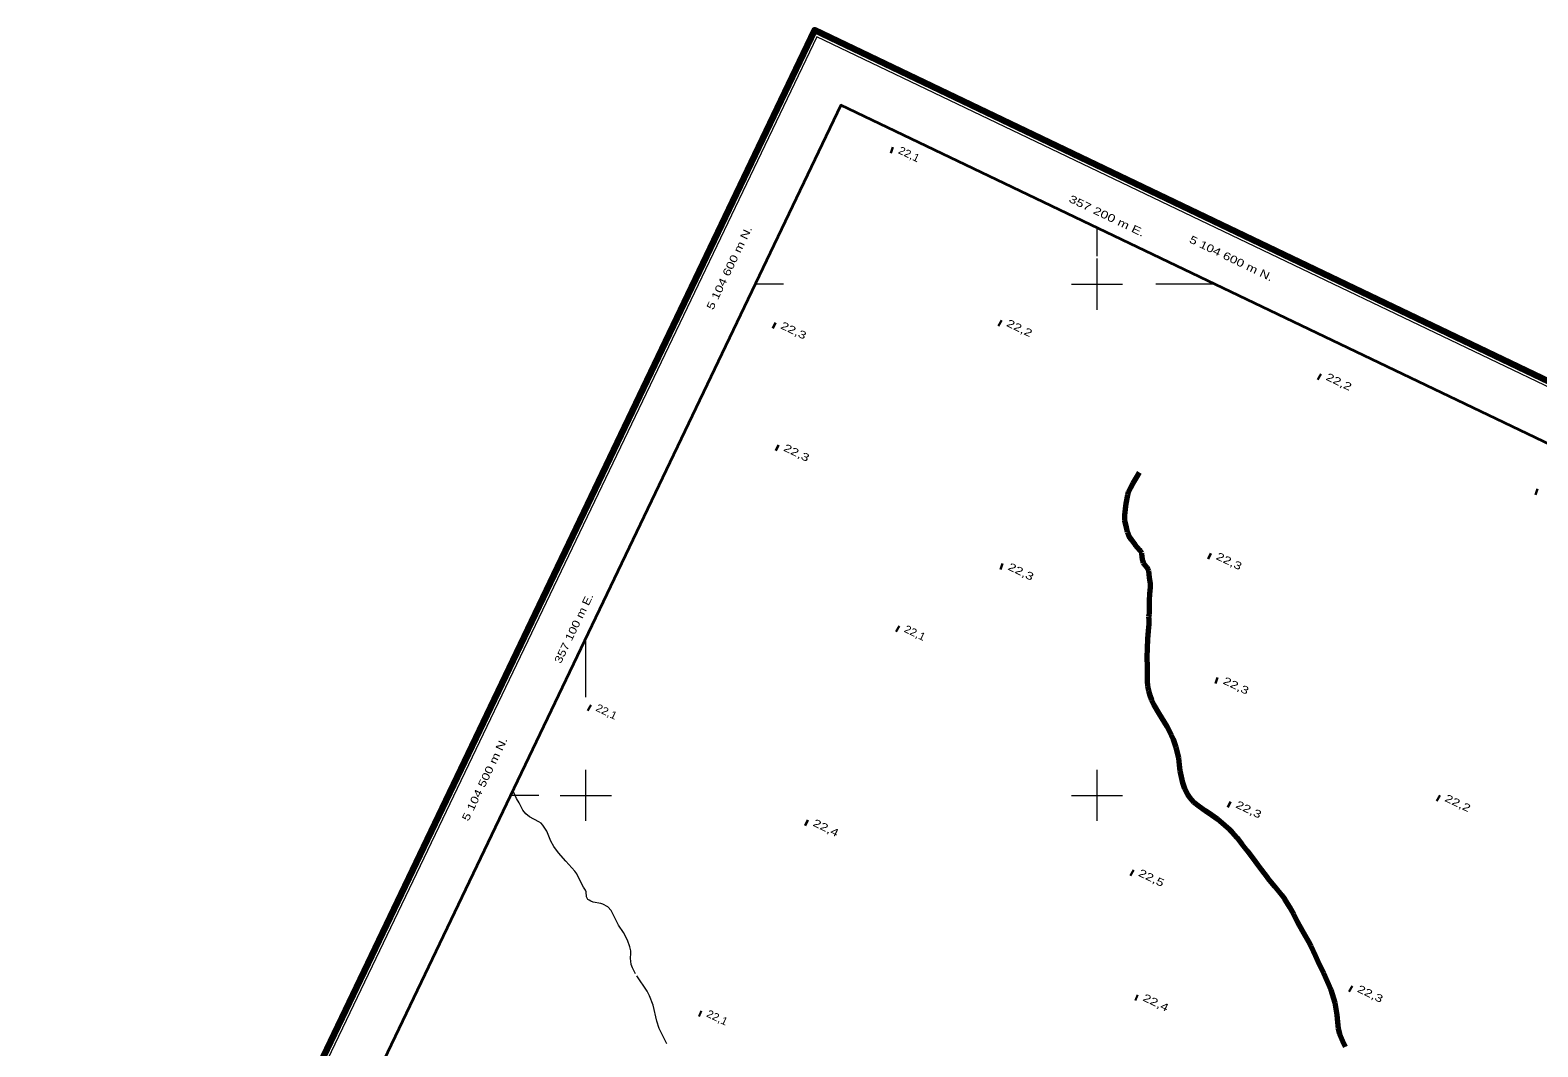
# Model space of a CAD drawing. Extents: x 356765 to 358572, y 5103174 to 5104650.
# Drawn here: x 356991.3 to 357286.2, y 5104450.8 to 5104649.7 of the extents above; entities that cross this region are included whole.
import ezdxf
from ezdxf.enums import TextEntityAlignment as Align

# ---------------------------------------------------------------- set-up
doc = ezdxf.new("R2010")
doc.units = 0
doc.header["$LTSCALE"] = 0.6
doc.linetypes.add('LONG_DASHED', pattern=[7.5, 6, -1.5])
for name, color, linetype, lineweight in [('2', 7, 'Continuous', 13), ('22', 7, 'Continuous', 35), ('3', 7, 'Continuous', 140), ('60', 7, 'Continuous', 13), ('61', 7, 'Continuous', 13)]:
    doc.layers.add(name, color=color, linetype=linetype, lineweight=lineweight)

msp = doc.modelspace()

# ---------------------------------------------------------------- linework, layer by layer
at = {"layer": '2', "linetype": 'LONG_DASHED'}
msp.add_lwpolyline([(357115.84, 5104451.38), (357114.36, 5104454.41), (357113.9, 5104455.84), (357113.16, 5104458.95), (357112.47, 5104460.83), (357112, 5104461.7), (357109.7, 5104465.13), (357109.1, 5104466.3), (357108.89, 5104466.93), (357108.78, 5104467.55), (357108.75, 5104468.12), (357108.83, 5104469.12), (357108.8, 5104469.58), (357108.6, 5104470.41), (357108.17, 5104471.66), (357107.4, 5104473.21), (357106.4, 5104474.62), (357104.95, 5104477.46), (357104.3, 5104478.19), (357103.3, 5104478.72), (357102.94, 5104478.84), (357101.44, 5104479.15), (357100.99, 5104479.29), (357100.64, 5104479.48), (357100.42, 5104479.67), (357100.25, 5104479.88), (357100.14, 5104480.16), (357100.06, 5104481.15), (357099.94, 5104481.5), (357099.56, 5104482.05), (357099.06, 5104482.92), (357098.23, 5104484.67), (357097.87, 5104485.21), (357096.08, 5104487.11), (357094.63, 5104488.78), (357093.71, 5104489.98), (357093.14, 5104491.07), (357092.37, 5104492.99), (357091.88, 5104493.82), (357091.58, 5104494.21), (357091.23, 5104494.55), (357090.81, 5104494.84), (357089, 5104495.8), (357088.27, 5104496.4), (357087.69, 5104497.15), (357086.94, 5104498.57), (357086.43, 5104499.42), (357085.82, 5104500.7), (357085.66, 5104500.98)], dxfattribs=at)
at = {"layer": '22', "linetype": 'LONG_DASHED', "lineweight": 70}
for points in [[(357210.22, 5104534.4), (357210.17, 5104534.99), (357210.24, 5104535.48), (357210.3, 5104535.79), (357210.3, 5104536.05), (357210.24, 5104537.18), (357210.26, 5104538.17), (357210.34, 5104539.38), (357210.45, 5104540.74), (357210.44, 5104541.42), (357210.28, 5104542.62), (357210.13, 5104543.94), (357210.04, 5104544.28), (357209.84, 5104544.59), (357209.29, 5104545.2), (357209.1, 5104545.51), (357208.99, 5104545.86), (357208.82, 5104546.62), (357208.76, 5104547.37), (357208.58, 5104547.76), (357208.4, 5104547.99), (357207.48, 5104549.05), (357206.72, 5104550), (357206.3, 5104550.67), (357205.99, 5104551.48), (357205.76, 5104552.38), (357205.45, 5104553.8), (357205.44, 5104554.84), (357205.6, 5104555.97), (357205.72, 5104557.12), (357206, 5104558.79), (357206.19, 5104559.3), (357206.63, 5104560.25), (357207.1, 5104561.07), (357207.86, 5104562.4), (357208.31, 5104563.18)], [(357248.61, 5104450.8), (357248.07, 5104451.92), (357247.48, 5104453.32), (357247.22, 5104454.38), (357247.08, 5104455.63), (357246.97, 5104457.09), (357246.74, 5104458.66), (357246.57, 5104459.46), (357246.1, 5104461.11), (357245.8, 5104461.94), (357245.11, 5104463.61), (357244.35, 5104465.26), (357243.54, 5104466.95), (357242.75, 5104468.72), (357241.9, 5104470.51), (357241.44, 5104471.38), (357240.49, 5104473.05), (357239.6, 5104474.55), (357239.22, 5104475.3), (357238.49, 5104476.75), (357237.69, 5104478.17), (357236.74, 5104479.68), (357236.15, 5104480.49), (357234.8, 5104482.2), (357233.42, 5104483.83), (357232.09, 5104485.49), (357231.51, 5104486.29), (357230.49, 5104487.76), (357229.44, 5104489.11), (357228.42, 5104490.42), (357227.45, 5104491.71), (357226.46, 5104492.83), (357225.96, 5104493.3), (357225, 5104494.15), (357223.54, 5104495.37), (357222.44, 5104496.16), (357221.25, 5104496.98), (357220.05, 5104497.83), (357218.97, 5104498.69), (357218.53, 5104499.13), (357218.13, 5104499.62), (357217.78, 5104500.16), (357217.2, 5104501.32), (357216.81, 5104502.48), (357216.51, 5104503.62), (357216.27, 5104504.79), (357216.13, 5104506), (357215.98, 5104507.28), (357215.7, 5104508.63), (357215.49, 5104509.37), (357214.95, 5104510.96), (357214.59, 5104511.79), (357213.73, 5104513.46), (357213.22, 5104514.3), (357212.13, 5104516.05), (357211.11, 5104517.78), (357210.7, 5104518.65), (357210.37, 5104519.55), (357210.13, 5104520.48), (357209.95, 5104521.4), (357209.88, 5104522.32), (357209.86, 5104523.25), (357209.87, 5104525.17), (357209.84, 5104527.03), (357209.88, 5104528.71), (357209.88, 5104528.84), (357209.96, 5104530.59), (357210.07, 5104532.19), (357210.19, 5104533.47), (357210.22, 5104534.4)]]:
    msp.add_lwpolyline(points, dxfattribs=at)
at = {"layer": '3'}
for p, q in [((357159.69, 5104626.32), (357160.05, 5104626.15)), ((357136.66, 5104592.06), (357137.02, 5104591.89)), ((357180.85, 5104592.5), (357181.21, 5104592.33)), ((357243.32, 5104582), (357243.68, 5104581.83)), ((357137.24, 5104568.12), (357137.6, 5104567.95)), ((357285.81, 5104559.48), (357286.17, 5104559.31)), ((357221.84, 5104546.91), (357222.2, 5104546.74)), ((357181.13, 5104544.86), (357181.49, 5104544.69)), ((357160.83, 5104532.7), (357161.19, 5104532.53)), ((357223.21, 5104522.56), (357223.57, 5104522.39)), ((357100.5, 5104517.27), (357100.86, 5104517.1)), ((357266.58, 5104499.58), (357266.94, 5104499.41)), ((357225.68, 5104498.33), (357226.04, 5104498.16)), ((357142.98, 5104494.76), (357143.34, 5104494.59)), ((357206.65, 5104484.96), (357207.01, 5104484.79)), ((357249.45, 5104462.28), (357249.81, 5104462.11)), ((357207.51, 5104460.56), (357207.87, 5104460.39)), ((357122.16, 5104457.42), (357122.52, 5104457.25))]:
    msp.add_line(p, q, dxfattribs=at)
at = {"layer": '60', "lineweight": 158}
msp.add_lwpolyline([(356765.24, 5103856.84), (358192.2, 5103173.84), (358571.69, 5103966.7), (357144.73, 5104649.7)], close=True, dxfattribs=at)
at = {"layer": '60'}
msp.add_lwpolyline([(356766.57, 5103857.31), (358191.72, 5103175.17), (358570.35, 5103966.23), (357145.2, 5104648.37)], close=True, dxfattribs=at)
at = {"layer": '60', "lineweight": 35}
msp.add_lwpolyline([(356779.89, 5103862.01), (357952.48, 5103300.77), (358322.47, 5104073.79), (357149.88, 5104635.03)], close=True, dxfattribs=at)
at = {"layer": '61'}
for p, q in [((357200, 5104605.5), (357200, 5104611.04)), ((357200, 5104595), (357200, 5104605)), ((357138.66, 5104600), (357133.12, 5104600)), ((357195, 5104600), (357205, 5104600)), ((357223.06, 5104600), (357211.48, 5104600)), ((357100, 5104519.24), (357100, 5104530.81)), ((357100, 5104495), (357100, 5104505)), ((357200, 5104495), (357200, 5104505)), ((357090.79, 5104500), (357085.25, 5104500)), ((357095, 5104500), (357105, 5104500)), ((357195, 5104500), (357205, 5104500))]:
    msp.add_line(p, q, dxfattribs=at)

# ---------------------------------------------------------------- texts
at = {"layer": '3'}
for s, rotation, width, p in [('22,1   ', 334.423, 1.1, (357160.98, 5104625.68)), ('22,3   ', 334.423, 1.35, (357137.95, 5104591.42)), ('22,2   ', 334.423, 1.35, (357182.14, 5104591.88)), ('22,2   ', 334.619, 1.35, (357244.62, 5104581.37)), ('22,3   ', 334.423, 1.35, (357138.53, 5104567.5)), ('22,3   ', 334.619, 1.35, (357223.14, 5104546.28)), ('22,3   ', 334.423, 1.35, (357182.42, 5104544.24)), ('22,1   ', 334.423, 1.1, (357162.12, 5104532.05)), ('22,3   ', 334.619, 1.35, (357224.51, 5104521.93)), ('22,1   ', 334.423, 1.1, (357101.79, 5104516.63)), ('22,2   ', 334.619, 1.35, (357267.88, 5104498.95)), ('22,3   ', 334.619, 1.35, (357226.98, 5104497.7)), ('22,4   ', 334.423, 1.35, (357144.27, 5104494.12)), ('22,5   ', 334.619, 1.35, (357207.95, 5104484.33)), ('22,4   ', 334.619, 1.35, (357208.81, 5104459.93)), ('22,3   ', 334.619, 1.35, (357250.75, 5104461.65)), ('22,1   ', 334.423, 1.1, (357123.45, 5104456.8))]:
    msp.add_text(s, height=1.5, rotation=rotation, dxfattribs=dict(at, width=width)).set_placement(p)
at = {"layer": '61'}
for s, rotation, width, p in [(' 357 200 m E.', 334.42, 1.35, (357201.2712, 5104612.8708)), (' 5 104 600 m N.', 64.42, 1.3, (357128.5792, 5104602.5712)), (' 5 104 600 m N.', 334.42, 1.3, (357225.6312, 5104604.5408)), (' 357 100 m E.', 64.42, 1.25, (357098.1706, 5104532.0762)), (' 5 104 500 m N.', 64.42, 1.3, (357080.7253, 5104502.5712))]:
    msp.add_text(s, height=1.5, rotation=rotation, dxfattribs=dict(at, width=width)).set_placement(p, align=Align.CENTER)

doc.saveas('drawing.dxf')
